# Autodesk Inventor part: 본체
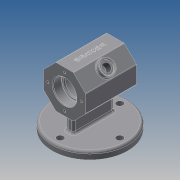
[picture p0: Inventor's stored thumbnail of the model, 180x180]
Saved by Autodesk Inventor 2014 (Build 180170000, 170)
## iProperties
Created: 2021-02
Part Number: 본체
Material: Generic
Document SubType Name: Modeling
Designer: kb542
Density: 1 g/cm^3
Appearance: Default
Mass: 206.202 g
Surface Area: 509.67 cm^2
Volume: 206.202 cm^3
Author: kb542
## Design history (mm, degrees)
sketch "스케치1" dims "d0" = 58
  geometry: L1 (-12.012, -29)-(-29, -12.012); L2 (-29, -12.012)-(-29, 12.012); L3 (-29, 12.012)-(-12.012, 29); L4 (-12.012, 29)-(12.012, 29); L5 (12.012, 29)-(29, 12.012); L6 (29, 12.012)-(29, -12.012); L7 (29, -12.012)-(12.012, -29); L8 (12.012, -29)-(-12.012, -29); 4 further points
  constraints: 16 end point, 2 coincident, 1 midpoint, 1 vertical, 1 vertical alignment, 19 other
extrude "돌출1" new body sketch "스케치1" distance "d1" = 70; taper "d2" = 0 deg
sketch "스케치2"
  geometry: L1 (0, 29)-(0, 12.012) reference; L2 (0, 12.012)-(0, -12.012) reference; L3 (0, 29)-(70, 29) reference; L4 (70, 12.012)-(70, 29) reference; L5 (70, -12.012)-(70, 12.012) reference; L6 (0, 16)-(12, 16); L7 (12, 16)-(12, 14); L8 (12, 14)-(15, 14); L9 (15, 14)-(15, 22); L10 (15, 22)-(55, 22); L11 (55, 22)-(55, 14); L12 (55, 14)-(58, 14); L13 (58, 14)-(58, 16); L14 (58, 16)-(70, 16); L15 (0, 0)-(70, 0); L16 (0, 16)-(0, 0); L17 (70, 16)-(70, 0)
  constraints: 24 end point, 6 parallel, 5 collinear, 4 perpendicular, 2 point on line, 1 midpoint
  dimensions: "d3" = 28 diameter of L8 L15; "d4" = 32 diameter of L6 L15; "d5" = 12 distance from line of L7 L1.end; "d6" = 3 distance between parallel lines of L9 L7; "d7" = 44 diameter of L10 L15
revolve "회전1" sketch "스케치2" stored, may be unused: angle "d8" = 90 deg
sketch "스케치3" dims "d9" = 46
  geometry: C1 r 16 at (0, 0) reference; 5 further points
  constraints: 2 vertical alignment, 1 coincident, 7 other
  dimensions: "d12" = 360 deg dimension on C1.centre point (0, 23) (derived)
hole "구멍1" sketch "스케치3" at (0, 23), (-23, 0), (0, -23), (23, 0) diameter "d14" = 3.242; stored, may be unused: countersink angle "d18" = 90 deg, drill point angle "d20" = 118 deg; dims "d15" = 8, "d16" = 4, "d17" = 2, "d19" = 10
node "작업 평면1"
sketch "스케치4"
  geometry: L1 (0, 0)-(24.042, 24.042); L2 (0, 0)-(0, 29); L3 (-12.012, 29)-(12.012, 29) reference
  constraints: 4 end point, 1 midpoint
  dimensions: "d21" = 34 distance of L1.end L1.start; "d22" = 45 deg angle of L2 L1
node "작업 평면2"
sketch "스케치5"
  geometry: L1 (-35, 29)-(35, 29) reference; L2 (-35, -12.012)-(-35, 12.012) reference; C1 r 10 at (0, 0); 1 further point
  constraints: 1 centre point
  dimensions: "d23" = 20 diameter of C1; "d24" = 29 distance from line of C1.centre L1; "d25" = 35 distance from line of C1.centre L2
extrude "돌출2" join sketch "스케치5" stored distance "d26" = 70; taper "d27" = 0 deg
hole "구멍2" diameter "d30" = 10.917; stored, may be unused: countersink angle "d34" = 90 deg, drill point angle "d36" = 118 deg; dims "d28" = 10, "d29" = 10, "d31" = 15, "d32" = 16, "d33" = 2, "d35" = 15
node "작업 평면3"
sketch "스케치6" dims "d39" = 82
  geometry: L1 (-29, 0)-(-29, 70) reference; C1 r 52 at (0, 35); C2 r 4.5 at (-41, 35); C3 r 4.5 at (0, -6); C4 r 4.5 at (41, 35); C5 r 4.5 at (0, 76); 3 further points
  constraints: 5 centre point, 2 horizontal alignment, 2 vertical alignment, 1 coincident, 1 midpoint, 11 other
  dimensions: "d38" = 104 diameter of C1; "d42" = 360 deg dimension on C1.centre C2.centre (derived); "d44" = 9 diameter of C2
extrude "돌출3" join sketch "스케치6" distance "d45" = 10; taper "d46" = 0 deg
sketch "스케치7"
  geometry: L1 (-5, -28)-(5, -28); L2 (5, -28)-(5, 28); L3 (5, 28)-(-5, 28); L4 (-5, 28)-(-5, -28); C1 r 4.5 at (-41, 0) reference; 3 further points
  constraints: 8 end point, 2 midpoint, 2 parallel, 1 horizontal, 1 horizontal alignment, 1 perpendicular, 1 vertical alignment
  dimensions: "d47" = 10 distance between parallel lines of L2 L4; "d48" = 56 distance between parallel lines of L3 L1
extrude "돌출4" join sketch "스케치7" stored distance "d49" = 10; taper "d50" = 0 deg
fillet "모깎기1" dims "d51" = 3, "d54" = 1
fillet "모깎기3" dims "d55" = 3, "d56" = 0.3
chamfer "모따기1" distance "d57" = 1; stored, may be unused: second distance "d58" = 2, angle "d59" = 45 deg
node "작업 평면4"
sketch "스케치8"
  geometry: L1 (-17.402, 70)-(-17.402, 0) reference; 2 further points
  constraints: 1 other
  dimensions: "d61" = 35 distance of point (11.598, 35) point (11.598, 0); "d62" = 29 distance from line of point (11.598, 35) L1
feature "엠보싱1" sketch "스케치8" dims "d0" = 58, "d63" = 0.5, "d64" = 0
node "솔리드1"
mirror "대칭1"
other parameters: "d37" = -62, "d60" = 21.5
